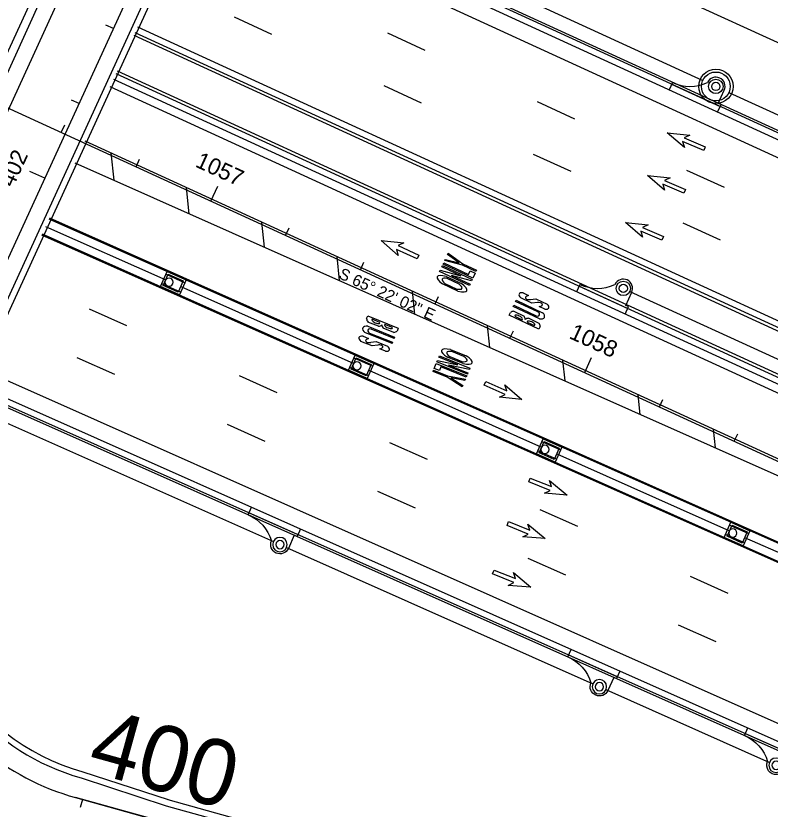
# Model space of a CAD drawing. Extents: x 468143 to 491361, y 1438528 to 1468730.
# Drawn here: x 487920.8 to 488104.2, y 1466882.5 to 1467075.2 of the extents above; entities that cross this region are included whole.
import ezdxf

# ---------------------------------------------------------------- set-up
doc = ezdxf.new("R2010")
doc.units = 0
doc.layers.add('Default', color=7, linetype='Continuous')
doc.layers.add('Xreference_dp', color=7, linetype='Continuous')

# ---------------------------------------------------------------- blocks, each defined once
blk = doc.blocks.new('POINT_DISPLAY')
at = {"layer": 'Default'}
blk.add_line((0, 0), (0, 0), dxfattribs=at)
blk = doc.blocks.new('InltCurb1_35')
at = {"layer": 'Default'}
for p, q in [((2.25, 2), (2.25, 5.5)), ((-10, 2), (-10, 0)), ((3, 2), (2.25, 2)), ((3, 0), (3, 2)), ((-10, 1.5), (3, 1.5))]:
    blk.add_line(p, q, dxfattribs=at)
for radius in [1.75, 1]:
    blk.add_circle((0, 5.5), radius, dxfattribs=at)
for centre, radius, start, end in [((0, 5.5), 2.25, 0, 180), ((-9.85, 12), 10, 269.1432, 319.4677)]:
    blk.add_arc(centre, radius, start, end, dxfattribs=at)
for p in [(0, 7.75), (-1.6, 6.2), (-1.22, 6.76), (-0.66, 7.12), (0, 7.25), (0, 7.25), (0.7, 7.1), (1.26, 6.72), (1.62, 6.16), (-1.75, 5.5), (-1.75, 5.5), (-1.62, 4.84), (-1.26, 4.28), (-0.7, 3.9), (0, 5.5), (0, 5.5), (0.66, 3.88), (1.22, 4.24), (1.6, 4.8), (1.75, 5.5), (1.75, 5.5), (0, 3.75), (0, 3.75), (0, 0), (0, 0)]:
    blk.add_blockref('POINT_DISPLAY', p, dxfattribs=at)
blk = doc.blocks.new('InltCurb7_40')
at = {"layer": 'Default'}
for p, q in [((2.5, 4), (-2.5, 4)), ((-2.5, 4), (-2.5, 0)), ((2.5, 0), (2.5, 4)), ((2.5, 3.25), (-2.5, 3.25)), ((-2.5, 0.75), (2.5, 0.75)), ((-2.5, 0), (2.5, 0))]:
    blk.add_line(p, q, dxfattribs=at)
blk.add_lwpolyline([(-2, 0.5), (2, 0.5), (2, 3.5), (-2, 3.5)], close=True, dxfattribs=at)
blk.add_circle((-1.04, 2.19), 1, dxfattribs=at)
for p in [(0, 4), (-2, 3.5), (-2, 2), (-2, 2), (0, 3.5), (0, 3.5), (0, 2), (0, 2), (2, 3.5), (2, 2), (2, 2), (-2, 0.5), (0, 0.5), (0, 0.5), (0, 0), (0, 0), (2, 0.5)]:
    blk.add_blockref('POINT_DISPLAY', p, dxfattribs=at)
blk = doc.blocks.new('JBottom70Dia')
at = {"layer": 'Default'}
for radius in [4.17, 3.5, 3.5]:
    blk.add_circle((0, 0), radius, dxfattribs=at)
for p in [(-2.44, 2.51), (-1.32, 3.24), (0, 3.5), (0, 3.5), (0, 3.5), (1.41, 3.2), (2.51, 2.44), (-3.5, 0), (-3.5, 0), (-3.2, 1.41), (0, 0), (0, 0), (0, 0), (3.24, 1.32), (-3.24, -1.32), (3.2, -1.41), (3.5, 0), (3.5, 0), (-2.51, -2.44), (-1.41, -3.2), (0, -3.5), (0, -3.5), (0, -3.5), (1.32, -3.24), (2.44, -2.51)]:
    blk.add_blockref('POINT_DISPLAY', p, dxfattribs=at)
blk = doc.blocks.new('DAMerge_2')
at = {"layer": 'Default'}
blk.add_lwpolyline([(0.71, -4.09), (0, -3.39), (3.95, 0.56), (2.42, 0.68), (7.31, 3.21), (4.77, -1.68), (4.66, -0.15), (0.71, -4.09)], dxfattribs=at)
blk = doc.blocks.new('BUS_7')
at = {"layer": 'Default'}
for p, q in [((0, 2.46), (0, 3.17)), ((0, 3.17), (8, 3.17)), ((3.33, 2.83), (1.33, 2.83)), ((1.33, 2.83), (1.33, 2.58)), ((3.33, 2.58), (3.33, 2.83)), ((6.67, 2.83), (4.67, 2.83)), ((4.67, 2.83), (4.67, 2.58)), ((6.67, 2.58), (6.67, 2.83)), ((8, 3.17), (8, 2.46)), ((3.38, 1.83), (0.62, 1.83)), ((0.97, 0.86), (8, 0.86)), ((8, 0.5), (2, 0.5)), ((7.38, 1.83), (4.62, 1.83)), ((8, 0.86), (8, 0.5)), ((0.8, -1.83), (2.26, -1.83)), ((8, -0.83), (0.89, -0.83)), ((2, -0.5), (8, -0.5)), ((3.08, -2.5), (4.23, -1.83)), ((4.23, -1.83), (7.2, -1.83)), ((8, -0.5), (8, -0.83)), ((3.77, -3.17), (0.8, -3.17)), ((4.93, -2.5), (3.77, -3.17)), ((7.2, -3.17), (5.74, -3.17))]:
    blk.add_line(p, q, dxfattribs=at)
for centre, major_axis, ratio, start_param, end_param in [((2, 2.83), (-2.08, 0), 0.64, 0.283794, 0.848062), ((2.33, 2.83), (-1.17, 0), 0.428571, 0.5411, 2.600493), ((2, 2.83), (-2.08, 0), 0.64, 2.293531, 2.857799), ((6, 2.83), (2.08, 0), 0.64, 3.425387, 3.989655), ((5.67, 2.83), (1.17, 0), 0.428571, 3.682692, 5.742086), ((6, 2.83), (2.08, 0), 0.64, 5.435123, 5.999391), ((2, 0), (2, 0), 0.5, 2.110653, 4.126703), ((2, 0), (0.667, 0), 0.75, 1.570796, 4.712389), ((2, -2.5), (-2, 0), 0.416667, 5.35589, 7.210481), ((2.67, -2.17), (-0.877, -0.48), 0.5, 4.914869, 8.056461), ((6, -2.5), (2, 0), 0.416667, 5.35589, 7.210481), ((5.33, -2.83), (-0.869, -0.495), 0.5, 1.760499, 4.902092)]:
    blk.add_ellipse(centre, major_axis=major_axis, ratio=ratio, start_param=start_param, end_param=end_param, dxfattribs=at)
blk = doc.blocks.new('BikeONLY_2')
at = {"layer": 'Default'}
for p, q in [((0.97, 1.833), (3.03, 1.833)), ((2.8, 1.667), (1.2, 1.667)), ((1.2, 1), (2.8, 1)), ((3.03, 0.833), (0.97, 0.833))]:
    blk.add_line(p, q, dxfattribs=at)
for points in [[(0, -0.167), (0, 0), (2.5, 0.458), (0, 0.458), (0, 0.625), (4, 0.625), (4, 0.458), (1.45, 0), (4, 0), (4, -0.167), (0, -0.167)], [(0.667, -1.042), (0, -1.042), (0, -0.375), (4, -0.375), (4, -0.542), (0.667, -0.542), (0.667, -1.042)], [(4, -1.833), (1.833, -1.417), (0, -1.417), (0, -1.25), (1.833, -1.25), (4, -0.833), (4, -1.003), (2.283, -1.333), (4, -1.664), (4, -1.833)]]:
    blk.add_lwpolyline(points, dxfattribs=at)
for major_axis, ratio, start_param, end_param in [((2, 0), 0.291667, 2.111896, 4.171289), ((1.333, 0), 0.3125, 2.214297, 4.068888), ((1.333, 0), 0.3125, 5.35589, 7.210481), ((2, 0), 0.291667, 5.253489, 7.312882)]:
    blk.add_ellipse((2, 1.333), major_axis=major_axis, ratio=ratio, start_param=start_param, end_param=end_param, dxfattribs=at)
blk = doc.blocks.new('DAMerge_6')
at = {"layer": 'Default'}
blk.add_lwpolyline([(0.71, -4.09), (0, -3.39), (3.95, 0.56), (2.42, 0.68), (7.31, 3.21), (4.77, -1.68), (4.66, -0.15), (0.71, -4.09)], dxfattribs=at)
blk = doc.blocks.new('BUS_8')
at = {"layer": 'Default'}
for p, q in [((0, 2.46), (0, 3.17)), ((0, 3.17), (8, 3.17)), ((3.33, 2.83), (1.33, 2.83)), ((1.33, 2.83), (1.33, 2.58)), ((3.33, 2.58), (3.33, 2.83)), ((6.67, 2.83), (4.67, 2.83)), ((4.67, 2.83), (4.67, 2.58)), ((6.67, 2.58), (6.67, 2.83)), ((8, 3.17), (8, 2.46)), ((3.38, 1.83), (0.62, 1.83)), ((0.97, 0.86), (8, 0.86)), ((8, 0.5), (2, 0.5)), ((7.38, 1.83), (4.62, 1.83)), ((8, 0.86), (8, 0.5)), ((0.8, -1.83), (2.26, -1.83)), ((8, -0.83), (0.89, -0.83)), ((2, -0.5), (8, -0.5)), ((3.08, -2.5), (4.23, -1.83)), ((4.23, -1.83), (7.2, -1.83)), ((8, -0.5), (8, -0.83)), ((3.77, -3.17), (0.8, -3.17)), ((4.93, -2.5), (3.77, -3.17)), ((7.2, -3.17), (5.74, -3.17))]:
    blk.add_line(p, q, dxfattribs=at)
for centre, major_axis, ratio, start_param, end_param in [((2, 2.83), (-2.08, 0), 0.64, 0.283794, 0.848062), ((2.33, 2.83), (-1.17, 0), 0.428571, 0.5411, 2.600493), ((2, 2.83), (-2.08, 0), 0.64, 2.293531, 2.857799), ((6, 2.83), (2.08, 0), 0.64, 3.425387, 3.989655), ((5.67, 2.83), (1.17, 0), 0.428571, 3.682692, 5.742086), ((6, 2.83), (2.08, 0), 0.64, 5.435123, 5.999391), ((2, 0), (2, 0), 0.5, 2.110653, 4.126703), ((2, 0), (0.667, 0), 0.75, 1.570796, 4.712389), ((2, -2.5), (-2, 0), 0.416667, 5.35589, 7.210481), ((2.67, -2.17), (-0.877, -0.48), 0.5, 4.914869, 8.056461), ((6, -2.5), (2, 0), 0.416667, 5.35589, 7.210481), ((5.33, -2.83), (-0.869, -0.495), 0.5, 1.760499, 4.902092)]:
    blk.add_ellipse(centre, major_axis=major_axis, ratio=ratio, start_param=start_param, end_param=end_param, dxfattribs=at)
blk = doc.blocks.new('BikeONLY_4')
at = {"layer": 'Default'}
for p, q in [((0.97, 1.833), (3.03, 1.833)), ((2.8, 1.667), (1.2, 1.667)), ((1.2, 1), (2.8, 1)), ((3.03, 0.833), (0.97, 0.833))]:
    blk.add_line(p, q, dxfattribs=at)
for points in [[(0, -0.167), (0, 0), (2.5, 0.458), (0, 0.458), (0, 0.625), (4, 0.625), (4, 0.458), (1.45, 0), (4, 0), (4, -0.167), (0, -0.167)], [(0.667, -1.042), (0, -1.042), (0, -0.375), (4, -0.375), (4, -0.542), (0.667, -0.542), (0.667, -1.042)], [(4, -1.833), (1.833, -1.417), (0, -1.417), (0, -1.25), (1.833, -1.25), (4, -0.833), (4, -1.003), (2.283, -1.333), (4, -1.664), (4, -1.833)]]:
    blk.add_lwpolyline(points, dxfattribs=at)
for major_axis, ratio, start_param, end_param in [((2, 0), 0.291667, 2.111896, 4.171289), ((1.333, 0), 0.3125, 2.214297, 4.068888), ((1.333, 0), 0.3125, 5.35589, 7.210481), ((2, 0), 0.291667, 5.253489, 7.312882)]:
    blk.add_ellipse((2, 1.333), major_axis=major_axis, ratio=ratio, start_param=start_param, end_param=end_param, dxfattribs=at)

msp = doc.modelspace()

# ---------------------------------------------------------------- linework, layer by layer
at = {"layer": 'Xreference_dp'}
for p, q in [((487372.29, 1467405.61), (488386.67, 1466939.92)), ((487416.58, 1467283.18), (488348.99, 1466855.64)), ((487878.29, 1466977.96), (487949.29, 1467132.79)), ((487880.11, 1466977.12), (487949.02, 1467127.41)), ((487883.23, 1466974.33), (487952.66, 1467125.74)), ((487896.86, 1466968.07), (487966.29, 1467119.49)), ((487896.86, 1466968.07), (487966.29, 1467119.49)), ((487903.94, 1466973.9), (487969.93, 1467117.82)), ((487905.34, 1466973.26), (487971.29, 1467117.1)), ((488379.21, 1466921.54), (487968, 1467110.09)), ((488379.42, 1466921.99), (487968.21, 1467110.55)), ((488378.58, 1466920.18), (487967.36, 1467108.73)), ((488376.92, 1466916.54), (487965.68, 1467105.11)), ((488003.33, 1467098.29), (488087.86, 1467059.53)), ((487983.11, 1467070.71), (487974.02, 1467074.88)), ((487944.57, 1467072.11), (487942.75, 1467072.94)), ((488361.91, 1466883.82), (487950.52, 1467072.45)), ((488361.91, 1466883.82), (487950.52, 1467072.45)), ((488360.97, 1466881.77), (487949.57, 1467070.41)), ((488361.29, 1466882.45), (487949.89, 1467071.09)), ((488020.39, 1467066.82), (488011.3, 1467070.99)), ((488357.02, 1466873.14), (487945.57, 1467061.79)), ((488356.08, 1466871.09), (487944.63, 1467059.75)), ((488356.7, 1466872.45), (487945.26, 1467061.11)), ((488355.24, 1466869.27), (487943.78, 1467057.94)), ((488019.47, 1467054.04), (488010.38, 1467058.21)), ((488094.23, 1467056.61), (488162.86, 1467025.14)), ((487936.23, 1467053.93), (487934.41, 1467054.76)), ((488056.75, 1467050.14), (488047.66, 1467054.31)), ((487931.9, 1467046.89), (487932.73, 1467048.7)), ((488349.2, 1466856.09), (487937.68, 1467044.79)), ((487943.96, 1467041.9), (487944.66, 1467035.27)), ((488055.83, 1467037.37), (488046.74, 1467041.54)), ((487935.21, 1467039.47), (488330.03, 1466863.88)), ((487950.08, 1467038.55), (487950.91, 1467040.37)), ((487927.89, 1467035.75), (487924.26, 1467037.41)), ((488093.11, 1467033.47), (488084.02, 1467037.64)), ((487962.27, 1467033.51), (487962.94, 1467027.14)), ((487968.26, 1467030.21), (487969.93, 1467033.85)), ((487928.9, 1467025.88), (488383.77, 1466823.62)), ((487929.01, 1467026.11), (488391.4, 1466820.5)), ((487980.57, 1467025.12), (487981.21, 1467019.01)), ((487928.06, 1467024.07), (487957.3, 1467011.06)), ((487986.44, 1467021.88), (487987.27, 1467023.7)), ((488092.19, 1467020.7), (488083.1, 1467024.86)), ((487927.11, 1467022.02), (488244.22, 1466881.02)), ((487927.22, 1467022.25), (488369.43, 1466825.62)), ((487998.87, 1467016.73), (487999.49, 1467010.89)), ((488004.62, 1467013.54), (488005.45, 1467015.36)), ((487960.96, 1467009.44), (488002.99, 1466990.74)), ((488017.18, 1467008.34), (488017.76, 1467002.76)), ((488070.13, 1467008.26), (488141.49, 1466975.54)), ((488022.8, 1467005.21), (488023.63, 1467007.02)), ((487938.63, 1467004.04), (487947.77, 1466999.98)), ((488035.48, 1466999.94), (488036.04, 1466994.63)), ((488040.98, 1466996.87), (488041.81, 1466998.69)), ((487935.69, 1466992.22), (487944.83, 1466988.15)), ((488053.78, 1466991.55), (488054.31, 1466986.5)), ((488059.16, 1466988.53), (488060.83, 1466992.17)), ((487912.06, 1466989.59), (488219.83, 1466852.74)), ((488006.65, 1466989.12), (488048.68, 1466970.43)), ((487975.18, 1466987.79), (487984.31, 1466983.73)), ((487909.74, 1466984.6), (488419.6, 1466757.89)), ((487910.37, 1466985.96), (488420.21, 1466759.26)), ((487909.53, 1466984.15), (488419.4, 1466757.43)), ((488072.08, 1466983.16), (488072.59, 1466978.38)), ((487908.05, 1466980.98), (487983.46, 1466947.45)), ((488077.34, 1466980.2), (488078.17, 1466982.02)), ((487972.24, 1466975.97), (487981.38, 1466971.9)), ((488090.39, 1466974.77), (488090.86, 1466970.25)), ((488095.52, 1466971.86), (488096.35, 1466973.68)), ((488011.73, 1466971.54), (488020.86, 1466967.48)), ((488052.34, 1466968.8), (488094.37, 1466950.11)), ((488008.79, 1466959.71), (488017.92, 1466955.65)), ((488048.28, 1466955.29), (488057.41, 1466951.22)), ((488098.03, 1466948.49), (488176.62, 1466913.54)), ((487986.66, 1466946.02), (488061.13, 1466912.91)), ((488045.34, 1466943.46), (488054.47, 1466939.4)), ((488084.83, 1466939.04), (488093.96, 1466934.97)), ((488081.89, 1466927.21), (488091.02, 1466923.15)), ((488064.33, 1466911.49), (488104.08, 1466893.81)), ((487936.71, 1466890.06), (487957.39, 1466883.29)), ((487937.12, 1466891.55), (487957.86, 1466884.76)), ((487956.32, 1466879.44), (487935.38, 1466885.25)), ((487956.32, 1466879.44), (487935.38, 1466885.25)), ((487935.38, 1466885.25), (488188.06, 1466815.2)), ((487937.05, 1466884.78), (487936.51, 1466882.86)), ((487957.8, 1466884.78), (488189.64, 1466820.51)), ((487957.39, 1466883.29), (488189.23, 1466819.03))]:
    msp.add_line(p, q, dxfattribs=at)
for radius, start in [(60, 155.3671), (60, 155.3671), (53.46, 165.4434), (55, 186.8898)]:
    msp.add_arc((487951.4, 1466943.07), radius, start, 254.5061, dxfattribs=at)

# ---------------------------------------------------------------- block references
for name, p, rotation in [('InltCurb1_35', (488088.75, 1467053.07), -24.632880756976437), ('JBottom70Dia', (488091.05, 1467058.07), 75.32156597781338), ('DAMerge_2', (488084.94, 1467041.2), 111.92563435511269), ('DAMerge_6', (488084.94, 1467041.2), 111.92563435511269), ('DAMerge_2', (488080.13, 1467030.84), 111.92563435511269), ('DAMerge_6', (488080.13, 1467030.84), 111.92563435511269), ('DAMerge_2', (488074.77, 1467019.41), 111.92563435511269), ('DAMerge_6', (488074.77, 1467019.41), 111.92563435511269), ('DAMerge_2', (488015.29, 1467014.98), 110.88826431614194), ('DAMerge_6', (488015.29, 1467014.98), 110.88826431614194), ('InltCurb1_35', (488066.25, 1467003.99), -24.632880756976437), ('BUS_7', (488049.37, 1467001.96), 154.82725300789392), ('BUS_8', (488049.37, 1467001.96), 154.82725300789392), ('BUS_7', (488005.2, 1466999.36), -22.066060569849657), ('BUS_8', (488005.2, 1466999.36), -22.066060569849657), ('DAMerge_2', (488038.24, 1466987.6), -68.71027206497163), ('DAMerge_6', (488038.24, 1466987.6), -68.71027206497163), ('DAMerge_2', (488049.04, 1466964.24), -66.96188651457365), ('DAMerge_6', (488049.04, 1466964.24), -66.96188651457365), ('DAMerge_2', (488043.76, 1466953.65), -66.96188651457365), ('DAMerge_6', (488043.76, 1466953.65), -66.96188651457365), ('DAMerge_2', (488040.23, 1466941.88), -66.96188651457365), ('DAMerge_6', (488040.23, 1466941.88), -66.96188651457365)]:
    msp.add_blockref(name, p, dxfattribs=dict(at, rotation=rotation))
for name, p, xscale, yscale, rotation in [('BikeONLY_2', (488031.66, 1467010.83), 2, 2, 154.82725300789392), ('BikeONLY_4', (488031.66, 1467010.83), 2, 2, 154.82725300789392), ('BikeONLY_2', (488023.36, 1466991.46), 1.9999999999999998, 2.0000000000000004, -22.066060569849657), ('BikeONLY_4', (488023.36, 1466991.46), 1.9999999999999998, 2.0000000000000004, -22.066060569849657)]:
    msp.add_blockref(name, p, dxfattribs=dict(at, xscale=xscale, yscale=yscale, rotation=rotation))
for name, p, yscale, rotation in [('InltCurb7_40', (487959.94, 1467012.08), -0.9999999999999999, -23.972703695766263), ('InltCurb7_40', (488005.63, 1466991.76), -0.9999999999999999, -23.972703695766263), ('InltCurb7_40', (488051.32, 1466971.44), -0.9999999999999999, -23.972703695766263), ('InltCurb1_35', (487987.29, 1466951.76), -1.0000000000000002, -23.97270369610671), ('InltCurb7_40', (488097.01, 1466951.13), -0.9999999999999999, -23.972703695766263), ('InltCurb1_35', (488064.97, 1466917.22), -1.0000000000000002, -23.97270369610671), ('InltCurb1_35', (488107.92, 1466898.13), -1.0000000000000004, -23.972703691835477)]:
    msp.add_blockref(name, p, dxfattribs=dict(at, yscale=yscale, rotation=rotation))

# ---------------------------------------------------------------- texts
for s, height, rotation, p in [('402', 4, 65.3671, (487920.19, 1467033.35)), ('1057', 4, 335.3671, (487964.23, 1467038.66)), ('S 65%%d 22\' 02" E', 2.8, 335.3671, (487999.12, 1467011.55)), ('1058', 4, 335.3671, (488055.13, 1466996.98)), ('400', 16, 344.5061, (487937.77, 1466891.78))]:
    msp.add_text(s, height=height, rotation=rotation, dxfattribs=at).set_placement(p)

doc.saveas('drawing.dxf')
